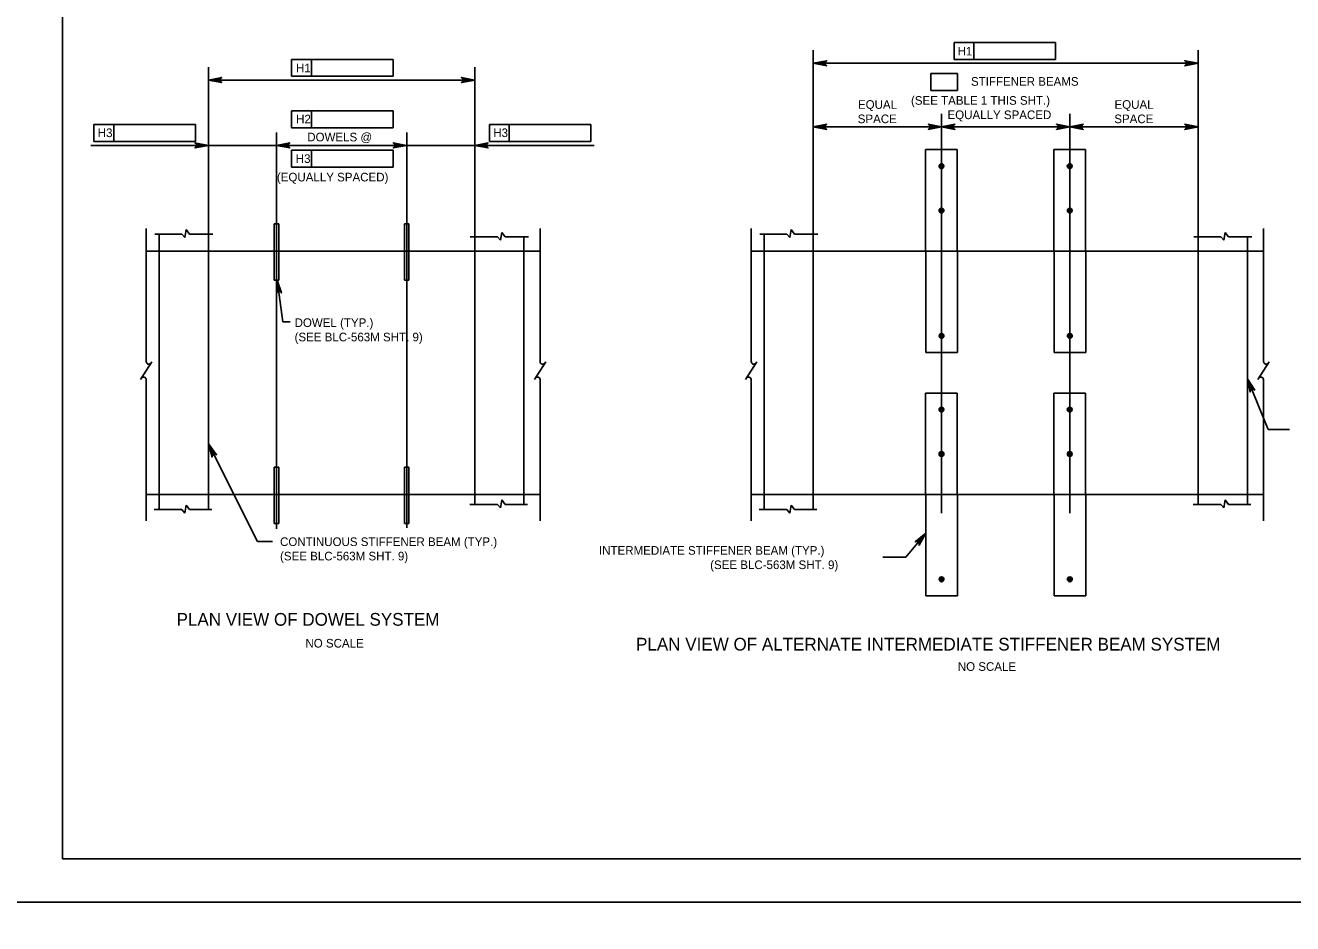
# Model space of a CAD drawing. Extents: x 638268 to 640277, y 295465 to 298435.
# Drawn here: x 639303.6 to 639744.6, y 297240 to 297552.5 of the extents above; entities that cross this region are included whole.
import ezdxf

# ---------------------------------------------------------------- set-up
doc = ezdxf.new("R2010")
doc.units = 0
for name, color, linetype in [('2', 7, 'Continuous'), ('3', 7, 'Continuous'), ('4', 7, 'Continuous'), ('PLT-BNDY', 7, 'Continuous')]:
    doc.layers.add(name, color=color, linetype=linetype)

# ---------------------------------------------------------------- blocks, each defined once
blk = doc.blocks.new('D')
at = {"layer": '3'}
for p, q in [((-0.48575, 0.574125), (-0.574125, 0.48575)), ((0.52325, -0.6115), (-0.574125, 0.48575)), ((0.6115, -0.52325), (-0.48575, 0.574125)), ((0.6115, -0.52325), (0.52325, -0.6115))]:
    blk.add_line(p, q, dxfattribs=at)

msp = doc.modelspace()

# ---------------------------------------------------------------- linework, layer by layer
at = {"layer": '2'}
for p, q in [((639316.46, 297262.46), (639316.46, 297826.46)), ((639482.71, 297474.02), (639345.64, 297474.02)), ((639734.43, 297474.02), (639556.15, 297474.02)), ((639482.71, 297389.31), (639345.64, 297389.31)), ((639734.43, 297389.31), (639556.15, 297389.31)), ((640102.46, 297262.46), (639316.46, 297262.46))]:
    msp.add_line(p, q, dxfattribs=at)
at = {"layer": '3'}
for p, q in [((639627.86, 297509.31), (639616.84, 297509.3)), ((639616.84, 297509.3), (639616.89, 297438.73)), ((639627.86, 297509.31), (639627.92, 297438.74)), ((639672.49, 297509.31), (639661.47, 297509.3)), ((639661.47, 297509.3), (639661.53, 297438.73)), ((639672.49, 297509.31), (639672.55, 297438.74)), ((639345.64, 297481.9), (639345.64, 297435.55)), ((639359.11, 297478.73), (639359.54, 297481.48)), ((639359.54, 297481.48), (639360.73, 297479.94)), ((639468.93, 297477.74), (639469.35, 297480.5)), ((639469.35, 297480.5), (639470.54, 297478.96)), ((639482.71, 297481.9), (639482.71, 297435.55)), ((639556.15, 297481.9), (639556.15, 297435.55)), ((639569.62, 297478.73), (639570.05, 297481.48)), ((639570.05, 297481.48), (639571.24, 297479.94)), ((639720.65, 297477.74), (639721.07, 297480.5)), ((639721.07, 297480.5), (639722.26, 297478.96)), ((639734.43, 297481.9), (639734.43, 297435.55)), ((639348.6, 297479.94), (639358.02, 297479.94)), ((639350.14, 297384.02), (639350.14, 297479.94)), ((639358.02, 297479.94), (639359.11, 297478.73)), ((639360.73, 297479.94), (639368.83, 297479.94)), ((639367.26, 297479.94), (639367.26, 297384.02)), ((639458.41, 297478.96), (639467.83, 297478.96)), ((639459.95, 297385.84), (639459.95, 297478.96)), ((639467.83, 297478.96), (639468.93, 297477.74)), ((639470.54, 297478.96), (639478.64, 297478.96)), ((639477.08, 297478.96), (639477.08, 297385.84)), ((639559.11, 297479.94), (639568.53, 297479.94)), ((639560.65, 297384.02), (639560.65, 297479.94)), ((639568.53, 297479.94), (639569.62, 297478.73)), ((639571.24, 297479.94), (639579.33, 297479.94)), ((639577.77, 297479.94), (639577.77, 297384.02)), ((639710.13, 297478.96), (639719.56, 297478.96)), ((639711.67, 297385.84), (639711.67, 297478.96)), ((639719.56, 297478.96), (639720.65, 297477.74)), ((639722.26, 297478.96), (639730.36, 297478.96)), ((639728.8, 297478.96), (639728.8, 297385.84)), ((639390.15, 297474.02), (639391.73, 297474.02)), ((639435.47, 297474.02), (639437.05, 297474.02)), ((639627.92, 297438.74), (639616.89, 297438.73)), ((639672.55, 297438.74), (639661.53, 297438.73)), ((639347.57, 297435.48), (639343.7, 297429.32)), ((639484.64, 297435.48), (639480.77, 297429.32)), ((639558.08, 297435.48), (639554.21, 297429.32)), ((639736.36, 297435.48), (639732.49, 297429.32)), ((639345.64, 297429.33), (639345.64, 297380.18)), ((639482.71, 297429.33), (639482.71, 297380.18)), ((639556.15, 297429.33), (639556.15, 297380.18)), ((639734.43, 297429.33), (639734.43, 297380.18)), ((639627.86, 297424.6), (639616.84, 297424.59)), ((639616.84, 297424.59), (639616.89, 297354.02)), ((639627.86, 297424.6), (639627.92, 297354.03)), ((639672.49, 297424.6), (639661.47, 297424.59)), ((639661.47, 297424.59), (639661.53, 297354.02)), ((639672.49, 297424.6), (639672.55, 297354.03)), ((639390.15, 297389.31), (639391.73, 297389.31)), ((639435.47, 297389.31), (639437.05, 297389.31)), ((639348.41, 297384.02), (639358.02, 297384.02)), ((639358.02, 297384.02), (639359.11, 297382.81)), ((639359.11, 297382.81), (639359.54, 297385.56)), ((639359.54, 297385.56), (639360.73, 297384.02)), ((639360.73, 297384.02), (639368.45, 297384.02)), ((639458.22, 297385.84), (639467.83, 297385.84)), ((639467.83, 297385.84), (639468.93, 297384.62)), ((639468.93, 297384.62), (639469.35, 297387.38)), ((639469.35, 297387.38), (639470.54, 297385.84)), ((639470.54, 297385.84), (639478.27, 297385.84)), ((639558.92, 297384.02), (639568.53, 297384.02)), ((639568.53, 297384.02), (639569.62, 297382.81)), ((639569.62, 297382.81), (639570.05, 297385.56)), ((639570.05, 297385.56), (639571.24, 297384.02)), ((639571.24, 297384.02), (639578.96, 297384.02)), ((639709.95, 297385.84), (639719.56, 297385.84)), ((639719.56, 297385.84), (639720.65, 297384.62)), ((639720.65, 297384.62), (639721.07, 297387.38)), ((639721.07, 297387.38), (639722.26, 297385.84)), ((639722.26, 297385.84), (639729.99, 297385.84)), ((639627.92, 297354.03), (639616.89, 297354.02)), ((639672.55, 297354.03), (639661.53, 297354.02))]:
    msp.add_line(p, q, dxfattribs=at)
for centre, radius in [((639622.35, 297503.54), 0.833), ((639622.35, 297503.54), 0.738), ((639622.35, 297503.54), 0.625), ((639622.35, 297503.54), 0.417), ((639622.35, 297503.54), 0.208), ((639666.99, 297503.54), 0.833), ((639666.99, 297503.54), 0.738), ((639666.99, 297503.54), 0.625), ((639666.99, 297503.54), 0.417), ((639666.99, 297503.54), 0.208), ((639622.36, 297488.09), 0.833), ((639622.36, 297488.09), 0.738), ((639667, 297488.09), 0.833), ((639667, 297488.09), 0.738), ((639622.36, 297488.09), 0.625), ((639622.36, 297488.09), 0.417), ((639622.36, 297488.09), 0.208), ((639667, 297488.09), 0.625), ((639667, 297488.09), 0.417), ((639667, 297488.09), 0.208), ((639622.4, 297444.49), 0.833), ((639622.4, 297444.49), 0.738), ((639622.4, 297444.49), 0.625), ((639622.4, 297444.49), 0.417), ((639667.04, 297444.49), 0.833), ((639667.04, 297444.49), 0.738), ((639667.04, 297444.49), 0.625), ((639667.04, 297444.49), 0.417), ((639622.4, 297444.49), 0.208), ((639667.04, 297444.49), 0.208), ((639622.35, 297418.84), 0.833), ((639622.35, 297418.84), 0.738), ((639622.35, 297418.84), 0.625), ((639622.35, 297418.84), 0.417), ((639622.35, 297418.84), 0.208), ((639666.99, 297418.84), 0.833), ((639666.99, 297418.84), 0.738), ((639666.99, 297418.84), 0.625), ((639666.99, 297418.84), 0.417), ((639666.99, 297418.84), 0.208), ((639622.36, 297403.39), 0.833), ((639622.36, 297403.39), 0.738), ((639622.36, 297403.39), 0.625), ((639622.36, 297403.39), 0.417), ((639622.36, 297403.39), 0.208), ((639667, 297403.39), 0.833), ((639667, 297403.39), 0.738), ((639667, 297403.39), 0.625), ((639667, 297403.39), 0.417), ((639667, 297403.39), 0.208), ((639622.4, 297359.79), 0.833), ((639622.4, 297359.79), 0.738), ((639622.4, 297359.79), 0.625), ((639622.4, 297359.79), 0.417), ((639622.4, 297359.79), 0.208), ((639667.04, 297359.79), 0.833), ((639667.04, 297359.79), 0.738), ((639667.04, 297359.79), 0.625), ((639667.04, 297359.79), 0.417), ((639667.04, 297359.79), 0.208)]:
    msp.add_circle(centre, radius, dxfattribs=at)
for centre, start, end in [((639346.55, 297435.55), 180, 330), ((639483.61, 297435.55), 180, 330), ((639557.06, 297435.55), 180, 330), ((639735.34, 297435.55), 180, 330), ((639344.73, 297429.25), 5.3286, 147.8672), ((639481.8, 297429.25), 5.3286, 147.8672), ((639555.24, 297429.25), 5.3286, 147.8672), ((639733.52, 297429.25), 5.3286, 147.8672)]:
    msp.add_arc(centre, 0.909, start, end, dxfattribs=at)
at = {"layer": '4'}
for p, q in [((639626.79, 297546.61), (639626.79, 297540.7)), ((639626.79, 297546.61), (639662.09, 297546.61)), ((639633.67, 297546.61), (639633.67, 297540.7)), ((639662.09, 297546.61), (639662.09, 297540.7)), ((639577.77, 297484.91), (639577.77, 297543.88)), ((639711.67, 297483.83), (639711.67, 297543.88)), ((639367.26, 297469.01), (639367.26, 297538)), ((639396.22, 297540.72), (639431.52, 297540.72)), ((639396.22, 297540.72), (639396.22, 297534.82)), ((639403.11, 297540.72), (639403.11, 297534.82)), ((639431.52, 297540.72), (639431.52, 297534.82)), ((639459.95, 297477.14), (639459.95, 297538)), ((639711.68, 297539.38), (639577.77, 297539.38)), ((639662.09, 297540.7), (639626.79, 297540.7)), ((639459.95, 297533.49), (639367.26, 297533.49)), ((639431.52, 297534.82), (639396.22, 297534.82)), ((639618.7, 297535.77), (639627.98, 297535.77)), ((639618.7, 297535.77), (639618.7, 297529.87)), ((639627.98, 297535.77), (639627.98, 297529.87)), ((639627.98, 297529.87), (639618.7, 297529.87)), ((639396.22, 297522.85), (639396.22, 297516.94)), ((639396.22, 297522.85), (639431.52, 297522.85)), ((639403.11, 297522.85), (639403.11, 297516.94)), ((639431.52, 297522.85), (639431.52, 297516.94)), ((639577.77, 297475.58), (639577.77, 297521.73)), ((639622.41, 297382.83), (639622.41, 297521.73)), ((639667.04, 297382.83), (639667.04, 297521.73)), ((639711.67, 297475.58), (639711.67, 297521.73)), ((639327.45, 297518.06), (639362.75, 297518.06)), ((639327.45, 297518.06), (639327.45, 297512.15)), ((639334.34, 297518.06), (639334.34, 297512.15)), ((639362.75, 297518.06), (639362.75, 297512.15)), ((639367.26, 297475.58), (639367.26, 297515.29)), ((639390.96, 297377.32), (639390.96, 297515.29)), ((639431.52, 297516.94), (639396.22, 297516.94)), ((639436.28, 297377.7), (639436.28, 297515.29)), ((639459.95, 297475.58), (639459.95, 297515.29)), ((639465.08, 297518.06), (639500.38, 297518.06)), ((639465.08, 297518.06), (639465.08, 297512.15)), ((639471.97, 297518.06), (639471.97, 297512.15)), ((639500.38, 297518.06), (639500.38, 297512.15)), ((639619.41, 297517.23), (639577.77, 297517.23)), ((639664.04, 297517.23), (639625.41, 297517.23)), ((639670.04, 297517.23), (639711.68, 297517.23)), ((639362.75, 297512.15), (639327.45, 297512.15)), ((639500.38, 297512.15), (639465.08, 297512.15)), ((639364.26, 297510.79), (639326.38, 297510.79)), ((639390.94, 297510.79), (639367.24, 297510.79)), ((639433.25, 297510.79), (639393.94, 297510.79)), ((639396.22, 297509.07), (639431.52, 297509.07)), ((639396.22, 297509.07), (639396.22, 297503.16)), ((639403.11, 297509.07), (639403.11, 297503.16)), ((639433.25, 297510.79), (639430.25, 297510.79)), ((639431.52, 297509.07), (639431.52, 297503.16)), ((639459.95, 297510.79), (639436.25, 297510.79)), ((639462.95, 297510.79), (639501.53, 297510.79)), ((639431.52, 297503.16), (639396.22, 297503.16)), ((639393.19, 297449.33), (639391.16, 297463.93)), ((639395.71, 297449.33), (639393.19, 297449.33)), ((639736.03, 297411.87), (639743.52, 297411.87)), ((639367.26, 297406.89), (639384.36, 297372.9)), ((639609.97, 297367.5), (639616.88, 297375.79)), ((639384.36, 297372.9), (639389.59, 297372.9)), ((639601.95, 297367.5), (639609.97, 297367.5))]:
    msp.add_line(p, q, dxfattribs=at)
for points in [[(639577.77, 297539.38), (639582.43, 297540.25), (639582.07, 297540.01), (639581.89, 297539.69), (639581.83, 297539.38), (639581.89, 297539.07), (639582.07, 297538.76), (639582.43, 297538.51), (639577.77, 297539.38), (639582.07, 297538.76), (639581.89, 297539.07), (639577.77, 297539.38), (639581.83, 297539.38), (639581.89, 297539.69), (639577.77, 297539.38), (639582.07, 297540.01)], [(639711.68, 297539.38), (639707.02, 297538.51), (639707.37, 297538.76), (639707.56, 297539.07), (639707.61, 297539.38), (639707.56, 297539.69), (639707.37, 297540.01), (639707.02, 297540.25), (639711.68, 297539.38), (639707.37, 297540.01), (639707.56, 297539.69), (639711.68, 297539.38), (639707.61, 297539.38), (639707.56, 297539.07), (639711.68, 297539.38), (639707.37, 297538.76)], [(639367.26, 297533.49), (639371.92, 297534.37), (639371.57, 297534.12), (639371.38, 297533.81), (639371.33, 297533.49), (639371.38, 297533.18), (639371.57, 297532.87), (639371.92, 297532.62), (639367.26, 297533.49), (639371.57, 297532.87), (639371.38, 297533.18), (639367.26, 297533.49), (639371.33, 297533.49), (639371.38, 297533.81), (639367.26, 297533.49), (639371.57, 297534.12)], [(639459.95, 297533.49), (639455.29, 297532.62), (639455.65, 297532.87), (639455.84, 297533.18), (639455.89, 297533.49), (639455.84, 297533.81), (639455.65, 297534.12), (639455.29, 297534.37), (639459.95, 297533.49), (639455.65, 297534.12), (639455.84, 297533.81), (639459.95, 297533.49), (639455.89, 297533.49), (639455.84, 297533.18), (639459.95, 297533.49), (639455.65, 297532.87)], [(639577.77, 297517.23), (639582.43, 297518.11), (639582.07, 297517.86), (639581.89, 297517.54), (639581.83, 297517.23), (639581.89, 297516.92), (639582.07, 297516.61), (639582.43, 297516.36), (639577.77, 297517.23), (639582.07, 297516.61), (639581.89, 297516.92), (639577.77, 297517.23), (639581.83, 297517.23), (639581.89, 297517.54), (639577.77, 297517.23), (639582.07, 297517.86)], [(639622.41, 297517.23), (639617.75, 297516.36), (639618.1, 297516.61), (639618.29, 297516.92), (639618.34, 297517.23), (639618.29, 297517.54), (639618.1, 297517.86), (639617.75, 297518.11), (639622.41, 297517.23), (639618.1, 297517.86), (639618.29, 297517.54), (639622.41, 297517.23), (639618.34, 297517.23), (639618.29, 297516.92), (639622.41, 297517.23), (639618.1, 297516.61)], [(639622.41, 297517.23), (639627.07, 297516.36), (639626.71, 297516.61), (639626.52, 297516.92), (639626.47, 297517.23), (639626.52, 297517.54), (639626.71, 297517.86), (639627.07, 297518.11), (639622.41, 297517.23), (639626.71, 297517.86), (639626.52, 297517.54), (639622.41, 297517.23), (639626.47, 297517.23), (639626.52, 297516.92), (639622.41, 297517.23), (639626.71, 297516.61)], [(639667.04, 297517.23), (639662.38, 297516.36), (639662.74, 297516.61), (639662.92, 297516.92), (639662.98, 297517.23), (639662.92, 297517.54), (639662.74, 297517.86), (639662.38, 297518.11), (639667.04, 297517.23), (639662.74, 297517.86), (639662.92, 297517.54), (639667.04, 297517.23), (639662.98, 297517.23), (639662.92, 297516.92), (639667.04, 297517.23), (639662.74, 297516.61)], [(639667.04, 297517.23), (639671.7, 297516.36), (639671.34, 297516.61), (639671.16, 297516.92), (639671.1, 297517.23), (639671.16, 297517.54), (639671.34, 297517.86), (639671.7, 297518.11), (639667.04, 297517.23), (639671.34, 297517.86), (639671.16, 297517.54), (639667.04, 297517.23), (639671.1, 297517.23), (639671.16, 297516.92), (639667.04, 297517.23), (639671.34, 297516.61)], [(639711.68, 297517.23), (639707.02, 297516.36), (639707.37, 297516.61), (639707.56, 297516.92), (639707.61, 297517.23), (639707.56, 297517.54), (639707.37, 297517.86), (639707.02, 297518.11), (639711.68, 297517.23), (639707.37, 297517.86), (639707.56, 297517.54), (639711.68, 297517.23), (639707.61, 297517.23), (639707.56, 297516.92), (639711.68, 297517.23), (639707.37, 297516.61)], [(639367.26, 297510.79), (639362.6, 297509.92), (639362.96, 297510.16), (639363.15, 297510.48), (639363.2, 297510.79), (639363.15, 297511.1), (639362.96, 297511.41), (639362.6, 297511.66), (639367.26, 297510.79), (639362.96, 297511.41), (639363.15, 297511.1), (639367.26, 297510.79), (639363.2, 297510.79), (639363.15, 297510.48), (639367.26, 297510.79), (639362.96, 297510.16)], [(639390.94, 297510.79), (639395.6, 297511.66), (639395.24, 297511.41), (639395.05, 297511.1), (639395, 297510.79), (639395.05, 297510.48), (639395.24, 297510.16), (639395.6, 297509.92), (639390.94, 297510.79), (639395.24, 297510.16), (639395.05, 297510.48), (639390.94, 297510.79), (639395, 297510.79), (639395.05, 297511.1), (639390.94, 297510.79), (639395.24, 297511.41)], [(639436.25, 297510.79), (639431.59, 297509.92), (639431.95, 297510.16), (639432.14, 297510.48), (639432.19, 297510.79), (639432.14, 297511.1), (639431.95, 297511.41), (639431.59, 297511.66), (639436.25, 297510.79), (639431.95, 297511.41), (639432.14, 297511.1), (639436.25, 297510.79), (639432.19, 297510.79), (639432.14, 297510.48), (639436.25, 297510.79), (639431.95, 297510.16)], [(639459.95, 297510.79), (639464.61, 297511.66), (639464.26, 297511.41), (639464.07, 297511.1), (639464.02, 297510.79), (639464.07, 297510.48), (639464.26, 297510.16), (639464.61, 297509.92), (639459.95, 297510.79), (639464.26, 297510.16), (639464.07, 297510.48), (639459.95, 297510.79), (639464.02, 297510.79), (639464.07, 297511.1), (639459.95, 297510.79), (639464.26, 297511.41)], [(639391.16, 297463.93), (639392.67, 297459.43), (639392.37, 297459.76), (639392.03, 297459.9), (639391.72, 297459.91), (639391.42, 297459.81), (639391.13, 297459.58), (639390.93, 297459.19), (639391.16, 297463.93), (639391.13, 297459.58), (639391.42, 297459.81), (639391.16, 297463.93), (639391.72, 297459.91), (639392.03, 297459.9), (639391.16, 297463.93), (639392.37, 297459.76)], [(639728.8, 297429.59), (639736.03, 297411.87)], [(639728.8, 297429.59), (639731.37, 297425.61), (639731, 297425.85), (639730.64, 297425.9), (639730.34, 297425.83), (639730.06, 297425.67), (639729.85, 297425.38), (639729.75, 297424.95), (639728.8, 297429.59), (639729.85, 297425.38), (639730.06, 297425.67), (639728.8, 297429.59), (639730.34, 297425.83), (639730.64, 297425.9), (639728.8, 297429.59), (639731, 297425.85)], [(639367.26, 297406.89), (639370.14, 297403.12), (639369.76, 297403.33), (639369.39, 297403.35), (639369.09, 297403.26), (639368.83, 297403.07), (639368.64, 297402.77), (639368.58, 297402.33), (639367.26, 297406.89), (639368.64, 297402.77), (639368.83, 297403.07), (639367.26, 297406.89), (639369.09, 297403.26), (639369.39, 297403.35), (639367.26, 297406.89), (639369.76, 297403.33)], [(639616.87, 297375.79), (639614.56, 297371.65), (639614.6, 297372.09), (639614.48, 297372.43), (639614.27, 297372.67), (639614, 297372.83), (639613.64, 297372.89), (639613.22, 297372.77), (639616.87, 297375.79), (639613.64, 297372.89), (639614, 297372.83), (639616.87, 297375.79), (639614.27, 297372.67), (639614.48, 297372.43), (639616.87, 297375.79), (639614.6, 297372.09)]]:
    msp.add_lwpolyline(points, dxfattribs=at)
for points in [[(639580.77, 297539.88), (639580.77, 297538.88), (639577.77, 297539.38)], [(639708.68, 297539.88), (639708.68, 297538.88), (639711.68, 297539.38)], [(639370.26, 297533.99), (639370.26, 297532.99), (639367.26, 297533.49)], [(639456.95, 297533.99), (639456.95, 297532.99), (639459.95, 297533.49)], [(639580.77, 297517.73), (639580.77, 297516.73), (639577.77, 297517.23)], [(639619.41, 297517.73), (639619.41, 297516.73), (639622.41, 297517.23)], [(639625.41, 297517.73), (639625.41, 297516.73), (639622.41, 297517.23)], [(639664.04, 297517.73), (639664.04, 297516.73), (639667.04, 297517.23)], [(639670.04, 297517.73), (639670.04, 297516.73), (639667.04, 297517.23)], [(639708.68, 297517.73), (639708.68, 297516.73), (639711.68, 297517.23)], [(639364.26, 297511.29), (639364.26, 297510.29), (639367.26, 297510.79)], [(639393.94, 297511.29), (639393.94, 297510.29), (639390.94, 297510.79)], [(639433.25, 297511.29), (639433.25, 297510.29), (639436.25, 297510.79)], [(639462.95, 297511.29), (639462.95, 297510.29), (639459.95, 297510.79)], [(639728.8, 297429.59), (639729.7, 297426.72), (639730.16, 297426.91)]]:
    msp.add_lwpolyline(points, close=True, dxfattribs=at)
at = {"layer": 'PLT-BNDY'}
for points in [[(639276.46, 297841.46), (640117.46, 297841.46), (640117.46, 297247.46), (639276.46, 297247.46)], [(639276.46, 297247.46), (640117.46, 297247.46), (640117.46, 296653.46), (639276.46, 296653.46)]]:
    msp.add_lwpolyline(points, close=True, dxfattribs=at)

# ---------------------------------------------------------------- block references
at = {"layer": '4', "xscale": 12.59905511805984, "yscale": 12.599055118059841, "rotation": -44.999951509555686}
for p in [(639390.94, 297474.02), (639436.26, 297474.02), (639390.94, 297389.32), (639436.26, 297389.32)]:
    msp.add_blockref('D', p, dxfattribs=at)

# ---------------------------------------------------------------- texts
at = {"layer": '4'}
for s, height, p in [('H1', 3, (639627.96, 297542.07)), ('H1', 3, (639397.74, 297536.18)), ('STIFFENER BEAMS', 3, (639632.63, 297531.53)), ('EQUAL', 3, (639593.3, 297523.51)), ('(SEE TABLE 1 THIS SHT.)', 3, (639611.76, 297524.92)), ('EQUAL', 3, (639682.57, 297523.51)), ('H2', 3, (639397.8, 297518.45)), ('SPACE', 3, (639593.23, 297518.51)), ('EQUALLY SPACED', 3, (639624.46, 297519.92)), ('SPACE', 3, (639682.5, 297518.51)), ('H3', 3, (639328.77, 297513.67)), ('DOWELS @', 3, (639401.67, 297512.17)), ('H3', 3, (639466.4, 297513.67)), ('H3', 3, (639397.67, 297504.67)), ('(EQUALLY SPACED)', 3, (639391.11, 297498.24)), ('DOWEL (TYP.)', 3, (639397.26, 297447.59)), ('(SEE BLC-563M SHT. 9)', 3, (639397.26, 297442.59)), ('CONTINUOUS STIFFENER BEAM (TYP.)', 3, (639392.2, 297371.36)), ('INTERMEDIATE STIFFENER BEAM (TYP.)', 3, (639503.18, 297368.34)), ('(SEE BLC-563M SHT. 9)', 3, (639392.2, 297366.36)), ('(SEE BLC-563M SHT. 9)', 3, (639541.87, 297363.34)), ('PLAN VIEW OF DOWEL SYSTEM', 4.4292, (639356.19, 297343.63)), ('NO SCALE', 3, (639401.04, 297336.04)), ('PLAN VIEW OF ALTERNATE INTERMEDIATE STIFFENER BEAM SYSTEM', 4.4292, (639516.09, 297334.99)), ('NO SCALE', 3, (639628.05, 297327.93))]:
    msp.add_text(s, height=height, dxfattribs=at).set_placement(p)

doc.saveas('drawing.dxf')
